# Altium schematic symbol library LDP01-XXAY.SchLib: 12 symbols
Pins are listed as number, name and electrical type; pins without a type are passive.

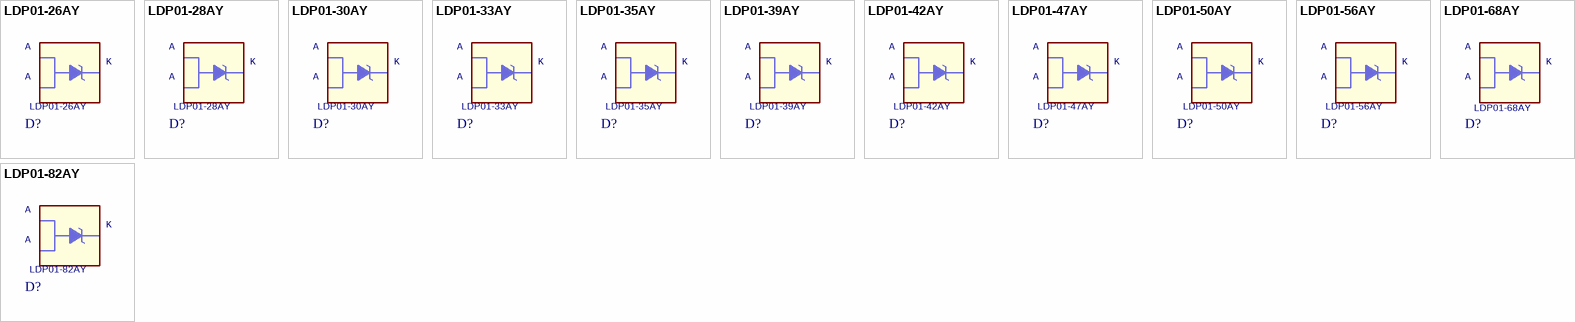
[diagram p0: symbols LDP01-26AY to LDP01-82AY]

## LDP01-26AY
designator D?
footprint ST_D2PAK
pins: 1 K, 2 A1, 3 A2

## LDP01-28AY
designator D?
footprint ST_D2PAK
pins: 1 K, 2 A1, 3 A2

## LDP01-30AY
designator D?
footprint ST_D2PAK
pins: 1 K, 2 A1, 3 A2

## LDP01-33AY
designator D?
footprint ST_D2PAK
pins: 1 K, 2 A1, 3 A2

## LDP01-35AY
designator D?
footprint ST_D2PAK
pins: 1 K, 2 A1, 3 A2

## LDP01-39AY
designator D?
footprint ST_D2PAK
pins: 1 K, 2 A1, 3 A2

## LDP01-42AY
designator D?
footprint ST_D2PAK
pins: 1 K, 2 A1, 3 A2

## LDP01-47AY
designator D?
footprint ST_D2PAK
pins: 1 K, 2 A1, 3 A2

## LDP01-50AY
designator D?
footprint ST_D2PAK
pins: 1 K, 2 A1, 3 A2

## LDP01-56AY
designator D?
footprint ST_D2PAK
pins: 1 K, 2 A1, 3 A2

## LDP01-68AY
designator D?
footprint ST_D2PAK
pins: 1 K, 2 A1, 3 A2

## LDP01-82AY
designator D?
footprint ST_D2PAK
pins: 1 K, 2 A1, 3 A2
